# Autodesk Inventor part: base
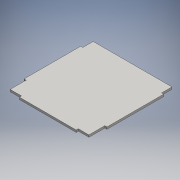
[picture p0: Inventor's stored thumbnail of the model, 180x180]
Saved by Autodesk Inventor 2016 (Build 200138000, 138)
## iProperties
Created: 2016-06
Part Number: base
Material: Genérico
Document SubType Name: Modeling
Designer: adm
Density: 1 g/cm^3
Appearance: Valor por defecto
Author: adm
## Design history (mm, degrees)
sketch "Boceto1"
  geometry: L1 (58, -33.541)-(58, 46.459); L2 (55, 61)-(-56, 61); L3 (-59, 46.459)-(-59, -33.541); L4 (-58, -56)-(58, 56); L5 (58, -56)-(-58, 56); L6 (-56, 61)-(-56, 46.459); L7 (-56, -33.541)-(-56, -56); L8 (-59, 46.459)-(-56, 46.459); L9 (55, 46.459)-(58, 46.459); L10 (55, -56)-(55, -33.541); L11 (55, 46.459)-(55, 61); L12 (-59, -33.541)-(-56, -33.541); L13 (55, -33.541)-(58, -33.541); L14 (-56, -54)-(-55.929, -54); L15 (55.929, -54)-(55, -54); L16 (-40, -56)-(-40, -59); L17 (40, -56)-(40, -59); L18 (-40, -59)-(40, -59); L19 (-56, -56)-(-40, -56); L20 (40, -56)-(55, -56); 2 further points
  constraints: 40 end point, 7 parallel, 7 perpendicular, 4 point on line, 2 horizontal, 2 midpoint
  dimensions: "d1" = 112 distance of L4.end L5.start; "d10" = 80 distance of L1.start L1.end; "d16" = 3 distance between parallel lines of L11 L1; "d17" = 3 distance between parallel lines of L10 L1; "d18" = 3 distance between parallel lines of L7 L3; "d22" = 59 distance from line of point (0, 0) L18; "d23" = 22.459 distance between parallel lines of L12 L19; "d25" = 120 distance between parallel lines of L2 L18
extrude "Extrusión1" new body sketch "Boceto1" distance "d14" = 3; taper "d15" = 0 deg
node "Sólido1"
other parameters: "d2" = 2, "d3" = 3, "d4" = 3, "d7" = 15, "d8" = 15, "d13" = 3
